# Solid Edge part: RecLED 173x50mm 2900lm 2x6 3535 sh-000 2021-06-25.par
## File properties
Author: radoslaw.kuczynski
Template: iso metric part.par
Last saved by: radoslaw.kuczynski
Revision: 1
Application: Solid Edge
Gęstość: 0,000 kg/m^3
Dokładność: 0,990
Username: radoslaw.kuczynski
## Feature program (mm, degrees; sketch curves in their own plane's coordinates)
body "unnamed Body 1"
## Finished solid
Body 1: solid body, 894 faces, 2325 edges, 1466 vertices, 2 separate solids.
  Faces by surface: plane 554, cylinder 176, spline 80, cone 26, torus 23, sphere 22, spun 7, swept 6
  Edges by curve: line 1540, circle 331, curve on surface 296, ellipse 66, intersection 54, spline 38
Bounding box of the edges (mm; curved faces can reach further): 49.500 x 5.000 x 172.200, from (-24.75, -3.5, -86.1) to (24.75, 1.5, 86.1).
Cylindrical faces by radius (mm): R0.15 x24, R0.2 x39, R0.2002 x2, R0.2169 x3, R0.25 x12, R0.3 x2, R0.3373 x3, R0.4 x8, R0.4006 x2, R0.4008 x2, R0.525 x2, R0.6 x12, R0.65 x24, R1 x7, R1.05 x12, R1.0894 x2, R1.1 x14, R1.75 x3, R1.7689 x1, R3 x1, R3.05 x1
Conical faces (half-angle, radius in mm at the cone's reference point): 0.5 deg R0.5056 x4, 0.5 deg R1.0082 x4, 1 deg R0.5511 x2, 10 deg R0.2132 x2, 10 deg R0.4132 x2, 18.4844 deg R1.0657 x4, 27.363 deg R0.6214 x2, 45 deg R0.575 x2, 45 deg R0.625 x4
Toroidal faces (ring radius, tube radius in mm): R0.1 r0.2 x1, R0.8 r0.2 x4, R0.8522 r0.3 x2, R0.9002 r0.2 x1, R0.9018 r0.2 x1, R1.3 r0.2 x2, R1.8254 r0.13 x12
Spherical faces by radius (mm): R0.2 x8, R0.6 x2, R1.7 x12
Planar faces by outward normal: +x 64, +y 24, +z 74, -x 62, -y 83, -z 80, oblique 167
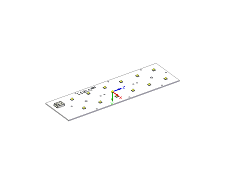
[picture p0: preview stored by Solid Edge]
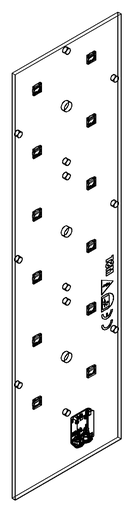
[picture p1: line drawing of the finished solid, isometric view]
